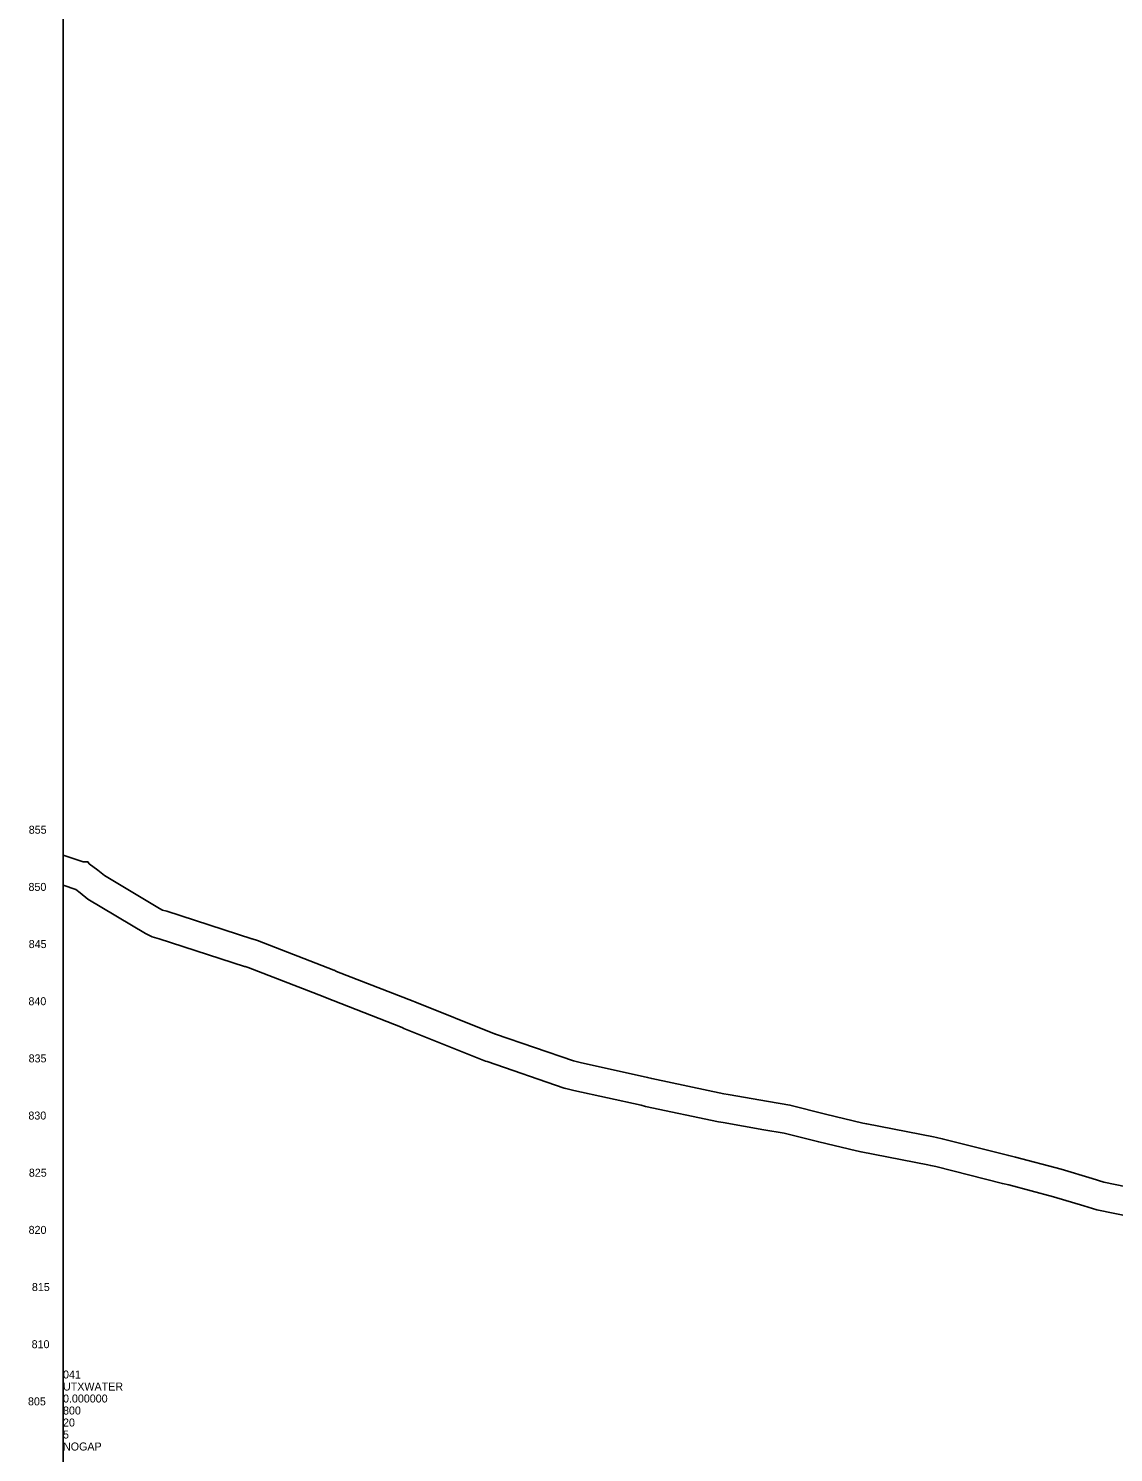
# Model space of a CAD drawing. Extents: x -12 to 4267, y -1006 to 1000.
# Drawn here: x 2954.8 to 3334.7, y -2.1 to 496.2 of the extents above; entities that cross this region are included whole.
import ezdxf

# ---------------------------------------------------------------- set-up
doc = ezdxf.new("R2010")
doc.units = 0
for name, color, linetype in [('GK_Cells', 7, 'Continuous'), ('PF_P_Sta_Elev_Text', 7, 'Continuous'), ('PF_X_Ground_Line', 7, 'Continuous'), ('UT_X_Water', 7, 'Continuous')]:
    doc.layers.add(name, color=color, linetype=linetype)

msp = doc.modelspace()

# ---------------------------------------------------------------- linework, layer by layer
at = {"layer": 'GK_Cells'}
msp.add_line((2966.93, -5.6), (2966.93, 994.4), dxfattribs=at)
at = {"layer": 'PF_X_Ground_Line'}
msp.add_lwpolyline([(2966.93, 206.9), (2967.64, 206.73), (2974.03, 204.61), (2975.66, 204.53), (2976.13, 203.92), (2979.14, 201.61), (2981.41, 199.75), (3000.68, 188.22), (3001.73, 187.68), (3003.33, 187.27), (3033.05, 177.65), (3033.15, 177.63), (3035.05, 177.04), (3061.75, 166.7), (3061.84, 166.67), (3062.73, 166.25), (3089.47, 155.82), (3090.13, 155.54), (3118.03, 144.37), (3118.15, 144.34), (3118.31, 144.3), (3145.6, 134.9), (3145.62, 134.9), (3148.01, 134.34), (3171.57, 129.12), (3173.07, 128.75), (3198.25, 123.46), (3199.75, 123.2), (3213.94, 120.7), (3221.4, 119.44), (3233.89, 116.31), (3246.95, 113.17), (3248.31, 112.89), (3271.7, 108.31), (3272.77, 108.08), (3274.73, 107.68), (3298.05, 101.77), (3300.41, 101.27), (3316.37, 96.99), (3327.21, 93.75), (3331.28, 92.53), (3343.19, 90.07)], dxfattribs=at)
at = {"layer": 'UT_X_Water'}
msp.add_lwpolyline([(2966.93, 196.43), (2966.93, 196.43), (2971.39, 194.95), (2972.92, 193.78), (2975.64, 191.55), (2995.82, 179.48), (2998.15, 178.28), (3000.54, 177.67), (3030.52, 167.96), (3030.68, 167.92), (3031.76, 167.59), (3057.98, 157.43), (3058.78, 157.06), (3085.68, 146.56), (3086.3, 146.3), (3114.87, 134.86), (3115.41, 134.72), (3142.41, 125.42), (3142.93, 125.25), (3145.8, 124.59), (3169.28, 119.38), (3170.83, 119), (3196.36, 113.64), (3198.02, 113.35), (3212.24, 110.84), (3219.35, 109.64), (3231.5, 106.6), (3244.75, 103.42), (3246.32, 103.09), (3269.69, 98.52), (3270.71, 98.3), (3272.49, 97.93), (3295.79, 92.02), (3298.09, 91.54), (3313.64, 87.36), (3324.34, 84.17), (3328.83, 82.82), (3340.92, 80.33)], dxfattribs=at)
msp.add_lwpolyline([(2966.93, 196.43), (2966.93, 196.43), (2971.39, 194.95), (2972.92, 193.78), (2975.64, 191.55), (2995.82, 179.48), (2998.15, 178.28), (3000.54, 177.67), (3030.52, 167.96), (3030.68, 167.92), (3031.76, 167.59), (3057.98, 157.43), (3058.78, 157.06), (3085.68, 146.56), (3086.3, 146.3), (3114.87, 134.86), (3115.41, 134.72), (3142.41, 125.42), (3142.93, 125.25), (3145.8, 124.59), (3169.28, 119.38), (3170.83, 119), (3196.36, 113.64), (3198.02, 113.35), (3212.24, 110.84), (3219.35, 109.64), (3231.5, 106.6), (3244.75, 103.42), (3246.32, 103.09), (3269.69, 98.52), (3270.71, 98.3), (3272.49, 97.93), (3295.79, 92.02), (3298.09, 91.54), (3313.64, 87.36), (3324.34, 84.17), (3328.83, 82.82), (3340.92, 80.33)], dxfattribs=at)

# ---------------------------------------------------------------- texts
at = {"layer": 'GK_Cells'}
for s, p in [('041', (2966.93, 23.8)), ('UTXWATER', (2966.93, 19.6)), ('0.000000', (2966.93, 15.4)), ('800', (2966.93, 11.2)), ('5', (2966.93, 2.8)), ('20', (2966.93, 7)), ('NOGAP', (2966.93, -1.4))]:
    msp.add_text(s, height=2.8, dxfattribs=at).set_placement(p)
at = {"layer": 'PF_P_Sta_Elev_Text'}
for s, p in [('855', (2954.94, 214.4)), ('850', (2954.85, 194.4)), ('845', (2954.92, 174.4)), ('840', (2954.83, 154.4)), ('835', (2954.89, 134.4)), ('830', (2954.81, 114.4)), ('825', (2954.98, 94.4)), ('820', (2954.89, 74.4)), ('815', (2956.04, 54.4)), ('810', (2955.95, 34.4)), ('805', (2954.67, 14.4))]:
    msp.add_text(s, height=2.8, dxfattribs=at).set_placement(p)

doc.saveas('drawing.dxf')
